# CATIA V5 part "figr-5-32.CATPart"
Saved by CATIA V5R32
Part number: Part1
Bounding box of the stored display mesh (mm): x -32.491 to 32.491, y -32.393 to 32.393, z 0 to 85.656
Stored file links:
  D:\PROJECTS\Project 2022\CATIA V5 6R 2022\Resources\Part Files\c05_catia_v5_6r2022_prt\figr-5-32.CATPart
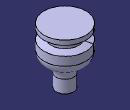
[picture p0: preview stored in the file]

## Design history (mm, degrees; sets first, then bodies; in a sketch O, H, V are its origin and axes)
Body1 (main body)
  Sketch1 on yz-plane, origin (0, 0, 0), H (0, 1, 0), V (0, 0, 1)
    axis line L1 (0, 0) -> (0, 100.0993)
    line L2 (0, 0) -> (13.3295, 0)
    line L3 (13.3295, 0) -> (13.3295, 19.6564)
    arc A1 centre (31.7623, 19.6564) radius 18.4328 from (13.3295, 19.6564) to (23.518, 36.1427) cw
    arc A2 centre (16.25, 50.6768) radius 16.25 from (23.518, 36.1427) to (32.5, 50.6768) ccw
    line L4 (32.5, 50.6768) -> (32.5, 85.6563)
    line L5 (32.5, 85.6563) -> (0, 85.6563)
    point P9 (0, 85.6563)
    line L6 (0, 85.6563) -> (0, 0)
    radius about axis L4 L1 = 32.5
    vertical: L1 V, L3 V, L4 V
    horizontal: L2 H, L5 H
    tangency: A1 L3, A2 L1, A2 A1, L4 A2, L6 A2
    coincidence: P9 L1
  Shaft1: profile Sketch1, axis Sketch1.L1, angle 360
  Sketch2 on yz-plane, origin (0, 0, 0), H (0, 1, 0), V (0, 0, 1)
    axis line L1 (0, 0) -> (0, 91.1904)
    point P1 (0, 0)
    point P2 (0, 91.1904)
    line L2 (32.5, 78.7512) -> (21.4593, 75.7196)
    line L3 (21.4593, 75.7196) -> (21.4593, 66.4534)
    line L4 (21.4593, 66.4534) -> (32.5, 63.9927)
    line L5 (32.5, 63.9927) -> (32.5, 78.7512)
    coincidence: P1 H, P2 V
    vertical: L1 V, L3 V, L5 V
  Groove1: profile Sketch2, axis Sketch2.L1, angle 360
